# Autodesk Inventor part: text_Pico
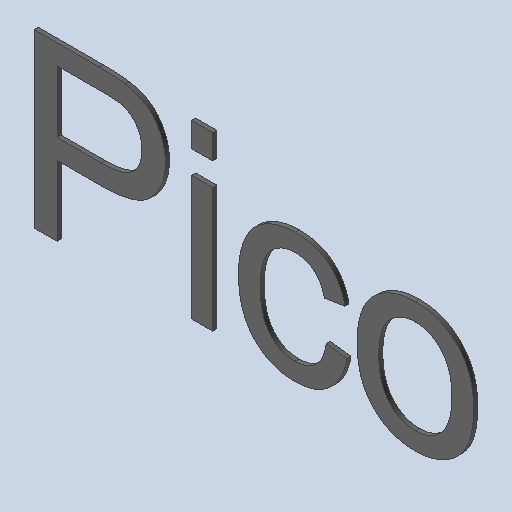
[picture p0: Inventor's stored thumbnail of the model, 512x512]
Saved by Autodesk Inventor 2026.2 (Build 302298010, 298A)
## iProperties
Created: 2026-10
Part Number: text_Pico
Material: Générique
Document SubType Name: Modeling
Designer: mel
Density: 1 g/cm^3
Appearance: Par défaut
Author: mel
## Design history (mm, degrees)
feature "Base1"
feature "Base2"
feature "Base3"
feature "Base4"
feature "Base5"
node "Solide1"
node "Solide2"
node "Solide3"
node "Solide4"
node "Solide5"
